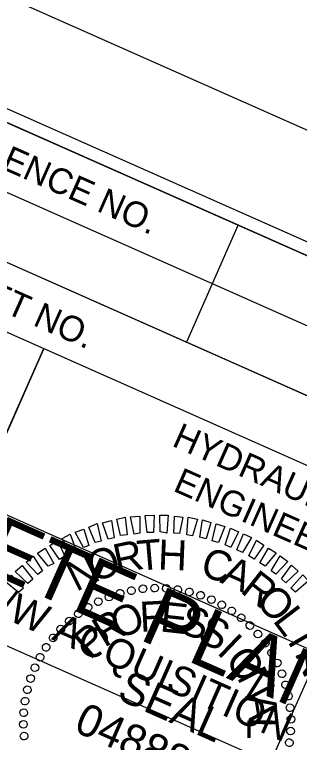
# Model space of a CAD drawing. Extents: x 1637682 to 2864602, y 842496 to 973236.
# Drawn here: x 1639528.1 to 1639584, y 843412.4 to 843555.1 of the extents above; entities that cross this region are included whole.
import ezdxf

# ---------------------------------------------------------------- set-up
doc = ezdxf.new("R2010")
doc.units = 0
for name, color, linetype in [('Old_Level_2', 7, 'Continuous'), ('Sheet Plan CELL', 7, 'Continuous'), ('Sheet Plot Border Inside CELL', 7, 'Continuous'), ('Sheet Plot Border Outside CELL', 7, 'Continuous'), ('Sheet Sticker Exception Certification CELL', 7, 'Continuous'), ('Sheet Sticker Incomplete CELL', 7, 'Continuous')]:
    doc.layers.add(name, color=color, linetype=linetype)

msp = doc.modelspace()

# ---------------------------------------------------------------- linework, layer by layer
at = {"layer": 'Old_Level_2'}
for p, q in [((1639553.33, 843442.53), (1639553.33, 843442.53)), ((1639555.61, 843442.7), (1639555.61, 843442.7)), ((1639557.87, 843442.65), (1639557.87, 843442.65)), ((1639548.83, 843441.7), (1639548.83, 843441.7)), ((1639551.03, 843442.19), (1639551.03, 843442.19)), ((1639560.13, 843442.37), (1639560.13, 843442.37)), ((1639562.41, 843441.86), (1639562.41, 843441.86)), ((1639564.61, 843441.28), (1639564.61, 843441.28)), ((1639544.56, 843440.04), (1639544.56, 843440.04)), ((1639546.63, 843440.93), (1639546.63, 843440.93)), ((1639566.75, 843440.43), (1639566.75, 843440.43)), ((1639542.55, 843438.91), (1639542.55, 843438.91)), ((1639568.81, 843439.39), (1639568.81, 843439.39)), ((1639570.73, 843438.18), (1639570.73, 843438.18)), ((1639540.61, 843437.68), (1639540.61, 843437.68)), ((1639572.57, 843436.89), (1639572.57, 843436.89)), ((1639538.85, 843436.21), (1639538.85, 843436.21)), ((1639574.31, 843435.36), (1639574.31, 843435.36)), ((1639537.17, 843434.65), (1639537.17, 843434.65)), ((1639535.64, 843432.91), (1639535.64, 843432.91)), ((1639575.87, 843433.68), (1639575.87, 843433.68)), ((1639534.35, 843431.08), (1639534.35, 843431.08)), ((1639577.34, 843431.92), (1639577.34, 843431.92)), ((1639578.57, 843429.98), (1639578.57, 843429.98)), ((1639533.14, 843429.15), (1639533.14, 843429.15)), ((1639532.1, 843427.09), (1639532.1, 843427.09)), ((1639579.7, 843427.97), (1639579.7, 843427.97)), ((1639580.59, 843425.9), (1639580.59, 843425.9)), ((1639531.25, 843424.95), (1639531.25, 843424.95)), ((1639530.67, 843422.76), (1639530.67, 843422.76)), ((1639581.36, 843423.7), (1639581.36, 843423.7)), ((1639581.85, 843421.5), (1639581.85, 843421.5)), ((1639530.16, 843420.47), (1639530.16, 843420.47)), ((1639529.88, 843418.21), (1639529.88, 843418.21)), ((1639582.18, 843419.2), (1639582.18, 843419.2)), ((1639582.35, 843416.92), (1639582.35, 843416.92)), ((1639529.83, 843415.95), (1639529.83, 843415.95)), ((1639556.09, 843416.44), (1639556.09, 843416.44)), ((1639582.31, 843414.66), (1639582.31, 843414.66)), ((1639530, 843413.67), (1639530, 843413.67))]:
    msp.add_line(p, q, dxfattribs=at)
for points in [[(1639551.56, 843453.26), (1639550.88, 843456.62), (1639552.7, 843456.76), (1639552.72, 843453.45)], [(1639554.12, 843453.54), (1639553.72, 843456.89), (1639555.5, 843456.93), (1639555.37, 843453.53)], [(1639556.67, 843453.66), (1639556.6, 843456.98), (1639558.29, 843456.95), (1639558, 843453.44)], [(1639559.36, 843453.43), (1639559.47, 843456.79), (1639561.15, 843456.59), (1639560.51, 843453.34)], [(1639543.94, 843451.6), (1639542.71, 843454.62), (1639544.36, 843455.29), (1639545.14, 843451.89)], [(1639546.5, 843452.28), (1639545.4, 843455.47), (1639547.13, 843455.93), (1639547.68, 843452.52)], [(1639548.94, 843452.95), (1639548.19, 843456.16), (1639549.83, 843456.55), (1639550.24, 843453.08)], [(1639561.93, 843453.08), (1639562.2, 843456.54), (1639563.98, 843456.19), (1639563.05, 843452.89)], [(1639564.47, 843452.63), (1639565, 843456.04), (1639566.65, 843455.51), (1639565.69, 843452.29)], [(1639541.64, 843450.59), (1639540.01, 843453.6), (1639541.69, 843454.2), (1639542.73, 843451.03)], [(1639566.9, 843451.95), (1639567.68, 843455.25), (1639569.39, 843454.75), (1639568.12, 843451.6)], [(1639569.41, 843451.17), (1639570.49, 843454.4), (1639572.06, 843453.68), (1639570.55, 843450.63)], [(1639539.18, 843449.47), (1639537.47, 843452.41), (1639539.05, 843453.21), (1639540.22, 843450.05)], [(1639571.7, 843450.14), (1639573.03, 843453.27), (1639574.6, 843452.55), (1639572.84, 843449.61)], [(1639536.96, 843448.25), (1639535.05, 843450.99), (1639536.55, 843452), (1639537.97, 843448.9)], [(1639574.05, 843448.98), (1639575.57, 843452.03), (1639577.03, 843451.07), (1639575.13, 843448.3)], [(1639534.7, 843446.94), (1639532.61, 843449.52), (1639534.15, 843450.46), (1639535.84, 843447.48)], [(1639576.2, 843447.62), (1639577.94, 843450.52), (1639579.42, 843449.6), (1639577.29, 843446.98)], [(1639532.67, 843445.35), (1639530.43, 843447.72), (1639531.78, 843448.91), (1639533.63, 843446.03)], [(1639578.43, 843446.05), (1639580.24, 843448.98), (1639581.71, 843447.9), (1639579.34, 843445.38)], [(1639530.77, 843443.55), (1639528.25, 843445.92), (1639529.6, 843447.1), (1639531.7, 843444.4)], [(1639580.48, 843444.45), (1639582.46, 843447.13), (1639583.75, 843446.01), (1639581.35, 843443.68)], [(1639528.91, 843441.83), (1639526.29, 843443.96), (1639527.55, 843445.19), (1639529.87, 843442.62)], [(1639582.28, 843442.66), (1639584.67, 843445.23), (1639585.77, 843444.08), (1639583.25, 843441.86)]]:
    msp.add_lwpolyline(points, close=True, dxfattribs=at)
for centre, major_axis in [((1639548.83, 843441.64), (-0.209, 0.723)), ((1639551.05, 843442.17), (-0.145, 0.739)), ((1639553.31, 843442.52), (-0.08, 0.749)), ((1639555.6, 843442.66), (-0.014, 0.753)), ((1639557.88, 843442.6), (0.051, 0.751)), ((1639560.16, 843442.35), (0.117, 0.744)), ((1639562.4, 843441.89), (0.181, 0.731)), ((1639546.66, 843440.91), (-0.271, 0.703)), ((1639564.6, 843441.25), (0.244, 0.712)), ((1639566.73, 843440.41), (0.305, 0.688)), ((1639542.55, 843438.9), (-0.389, 0.645)), ((1639544.56, 843439.99), (-0.331, 0.676)), ((1639568.77, 843439.39), (0.364, 0.659)), ((1639540.65, 843437.63), (-0.443, 0.608)), ((1639570.73, 843438.2), (0.42, 0.625)), ((1639538.86, 843436.2), (-0.495, 0.568)), ((1639572.57, 843436.84), (0.473, 0.586)), ((1639537.2, 843434.63), (-0.542, 0.522)), ((1639574.28, 843435.33), (0.522, 0.542)), ((1639575.86, 843433.67), (0.568, 0.495)), ((1639535.69, 843432.91), (-0.586, 0.473)), ((1639577.29, 843431.88), (0.608, 0.443)), ((1639534.33, 843431.07), (-0.625, 0.42)), ((1639533.14, 843429.12), (-0.659, 0.364)), ((1639578.56, 843429.98), (0.645, 0.389)), ((1639579.65, 843427.97), (0.676, 0.331)), ((1639532.12, 843427.07), (-0.688, 0.305)), ((1639531.28, 843424.94), (-0.712, 0.244)), ((1639580.57, 843425.87), (0.703, 0.271)), ((1639581.29, 843423.7), (0.723, 0.209)), ((1639530.64, 843422.74), (-0.731, 0.181)), ((1639530.18, 843420.5), (-0.744, 0.117)), ((1639581.83, 843421.48), (0.739, 0.145)), ((1639582.17, 843419.22), (0.749, 0.08)), ((1639529.93, 843418.23), (-0.751, 0.051)), ((1639582.32, 843416.93), (0.753, 0.014)), ((1639529.87, 843415.94), (-0.753, -0.014)), ((1639582.26, 843414.65), (0.751, -0.051)), ((1639530.01, 843413.65), (-0.749, -0.08)), ((1639582.01, 843412.37), (0.744, -0.117))]:
    msp.add_ellipse(centre, major_axis=major_axis, ratio=0.999708, dxfattribs=at)
at = {"layer": 'Sheet Plan CELL'}
for p, q in [((1639452.57, 843553.04), (1639635.44, 843471.94)), ((1639447.5, 843541.57), (1639630.37, 843460.51)), ((1639447.5, 843541.57), (1639630.37, 843460.51)), ((1639571.92, 843513.76), (1639561.83, 843490.89)), ((1639533.9, 843489.6), (1639488.32, 843386.79))]:
    msp.add_line(p, q, dxfattribs=at)
for points in [[(1639640.56, 843483.39), (1638269.28, 844091.43), (1637843.67, 843131.56), (1639214.92, 842523.53)], [(1639457.67, 843564.51), (1639640.56, 843483.39), (1639630.37, 843460.51), (1639447.5, 843541.57)], [(1639442.43, 843530.16), (1639533.9, 843489.6), (1639488.29, 843386.75), (1639396.85, 843427.32)], [(1639533.9, 843489.6), (1639625.31, 843449.08), (1639579.71, 843346.22), (1639488.29, 843386.75)]]:
    msp.add_lwpolyline(points, close=True, dxfattribs=at)
at = {"layer": 'Sheet Plot Border Inside CELL'}
msp.add_lwpolyline([(1637702.34, 843191.48), (1639225.33, 842516.19), (1639652.97, 843480.61), (1638129.98, 844155.92)], close=True, dxfattribs=at)
at = {"layer": 'Sheet Plot Border Outside CELL'}
msp.add_lwpolyline([(1637682.35, 843178.46), (1639221.34, 842496.06), (1639665.19, 843497.07), (1638126.2, 844179.47)], close=True, dxfattribs=at)
msp.add_lwpolyline([(1637682.35, 843178.46), (1639221.34, 842496.06), (1639665.19, 843497.07), (1638126.2, 844179.47)], close=True, dxfattribs=at)
at = {"layer": 'Sheet Sticker Incomplete CELL'}
msp.add_lwpolyline([(1639443.9, 843467.97), (1639453.43, 843489.46), (1639587.81, 843429.87), (1639578.29, 843408.39)], close=True, dxfattribs=at)

# ---------------------------------------------------------------- texts
at = {"layer": 'Old_Level_2'}
for s, height, rotation, p in [('R', 5.9, 12.1076, (1639548.21, 843445.32)), ('T', 5.9, 4.9069, (1639552.38, 843446.05)), ('H', 5.9, 357.7066, (1639556.18, 843446.32)), ('O', 5.9, 19.3089, (1639543.62, 843443.73)), ('C', 5.9, 343.307, (1639564.31, 843445.15)), ('N', 5.9, 26.5106, (1639540.22, 843441.88)), ('A', 5.9, 336.1075, (1639568.24, 843443.83)), ('R', 5.9, 321.7082, (1639572.2, 843441.93)), ('O', 5.9, 314.5083, (1639575.13, 843439.84)), ('F', 5.9, 3.0542, (1639552.81, 843434.06)), ('E', 5.9, 353.6982, (1639556.51, 843434.2)), ('O', 5.9, 21.7684, (1639548.43, 843432.56)), ('S', 5.9, 344.3427, (1639560.26, 843433.81)), ('L', 5.9, 307.308, (1639578.61, 843436.27)), ('R', 5.9, 31.1268, (1639545.75, 843430.91)), ('S', 5.9, 334.9875, (1639563.75, 843432.39)), ('P', 5.9, 40.486, (1639542.91, 843428.48)), ('I', 5.9, 300.1073, (1639581.54, 843432.31)), ('I', 5.9, 316.2767, (1639567.6, 843429.96)), ('N', 5.9, 292.906, (1639582.98, 843429.94)), ('O', 5.9, 306.9206, (1639569.24, 843428.48)), ('N', 5.9, 297.5638, (1639571.66, 843425.19)), ('SEAL', 6.273, 336.0871, (1639547.98, 843421)), ('A', 5.9, 278.8474, (1639573.34, 843421.52)), ('048883', 6.275, 336.0871, (1639539.51, 843414.69)), ('L', 5.9, 269.488, (1639573.82, 843417.4))]:
    msp.add_text(s, height=height, rotation=rotation, dxfattribs=at).set_placement(p)
at = {"layer": 'Sheet Plan CELL'}
for s, height, p in [('PROJECT REFERENCE NO.', 5.0001, (1639474.42, 843547.53)), ('R/W SHEET NO.', 5.0001, (1639495.88, 843510.07)), ('HYDRAULICS', 5, (1639558.8, 843470.6)), ('ENGINEER', 5, (1639559.01, 843461.8))]:
    msp.add_text(s, height=height, rotation=336.0871, dxfattribs=at).set_placement(p)
at = {"layer": 'Sheet Sticker Exception Certification CELL'}
msp.add_text('DOCUMENT NOT CONSIDERED FINAL', height=5.5, rotation=336.0871, dxfattribs=at).set_placement((1639411.92, 843409.32))
msp.add_text('DOCUMENT NOT CONSIDERED FINAL', height=5.5, rotation=336.0871, dxfattribs=at).set_placement((1639411.92, 843409.32))
at = {"layer": 'Sheet Sticker Incomplete CELL'}
for s, height, p in [('INCOMPLETE PLANS', 11.52, (1639456.83, 843475.04)), ('DO NOT USE FOR R/W ACQUISITION', 5.76, (1639456.98, 843467.37))]:
    msp.add_text(s, height=height, rotation=336.0871, dxfattribs=at).set_placement(p)

doc.saveas('drawing.dxf')
